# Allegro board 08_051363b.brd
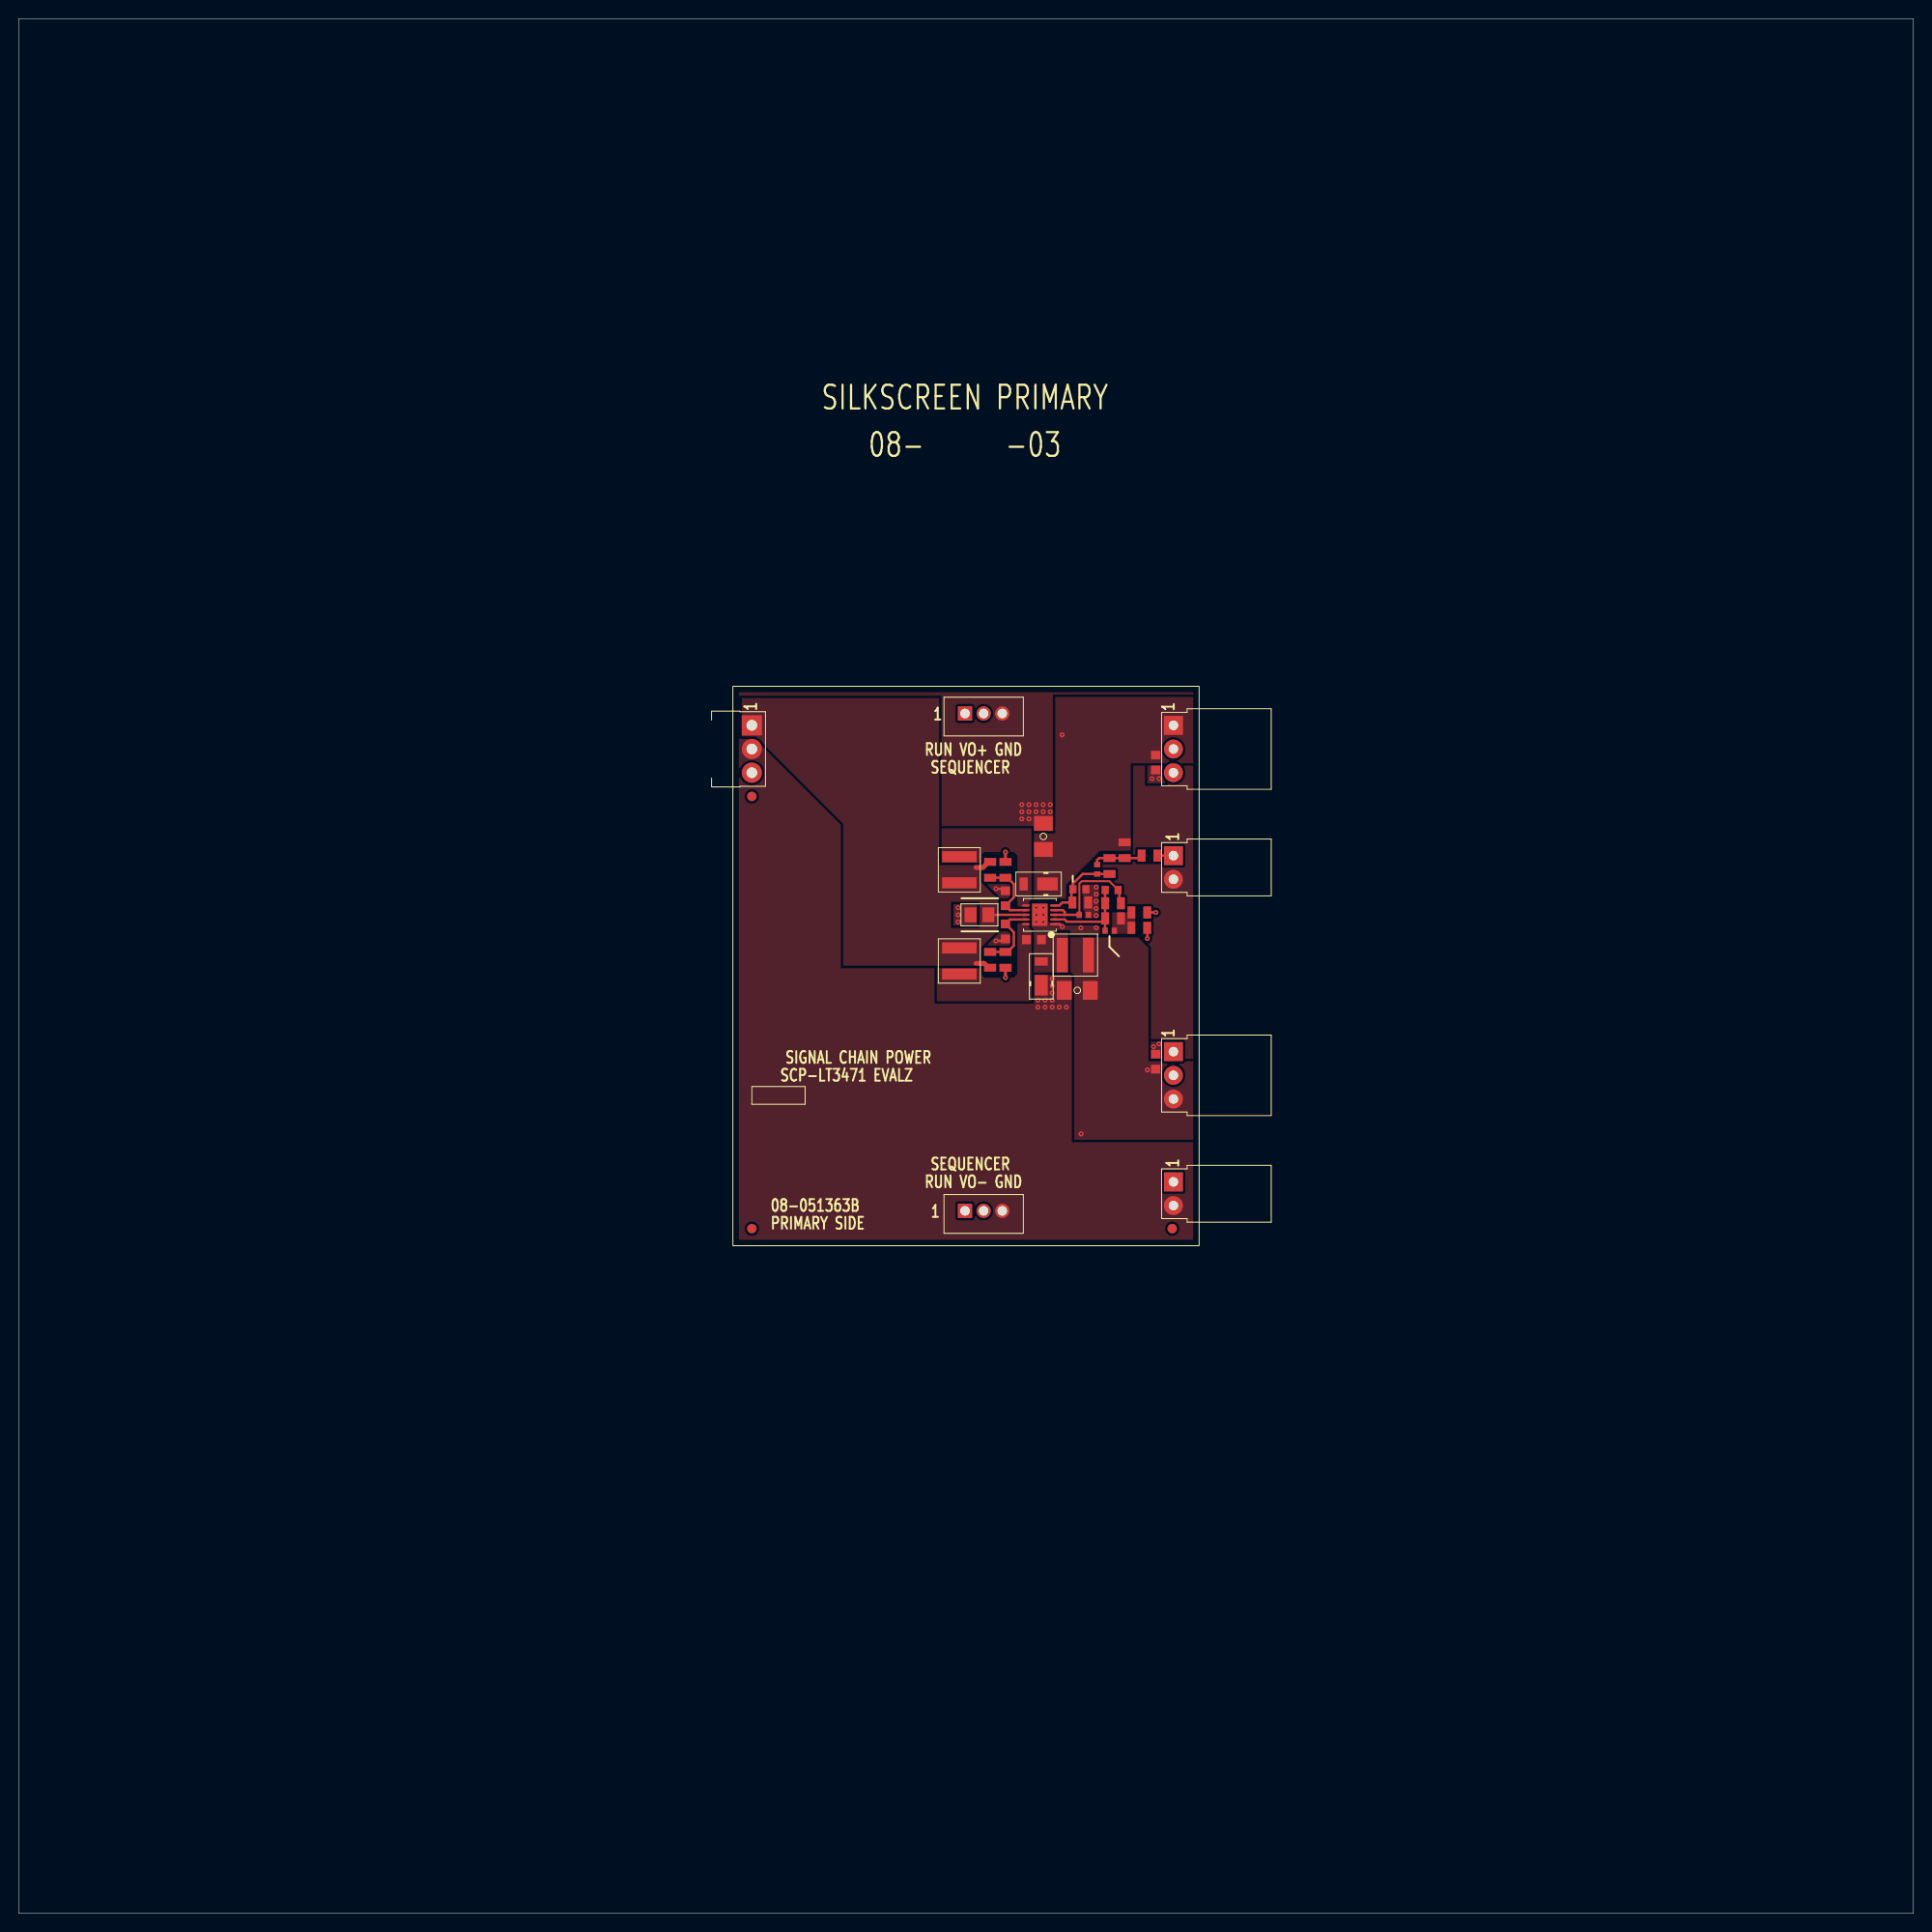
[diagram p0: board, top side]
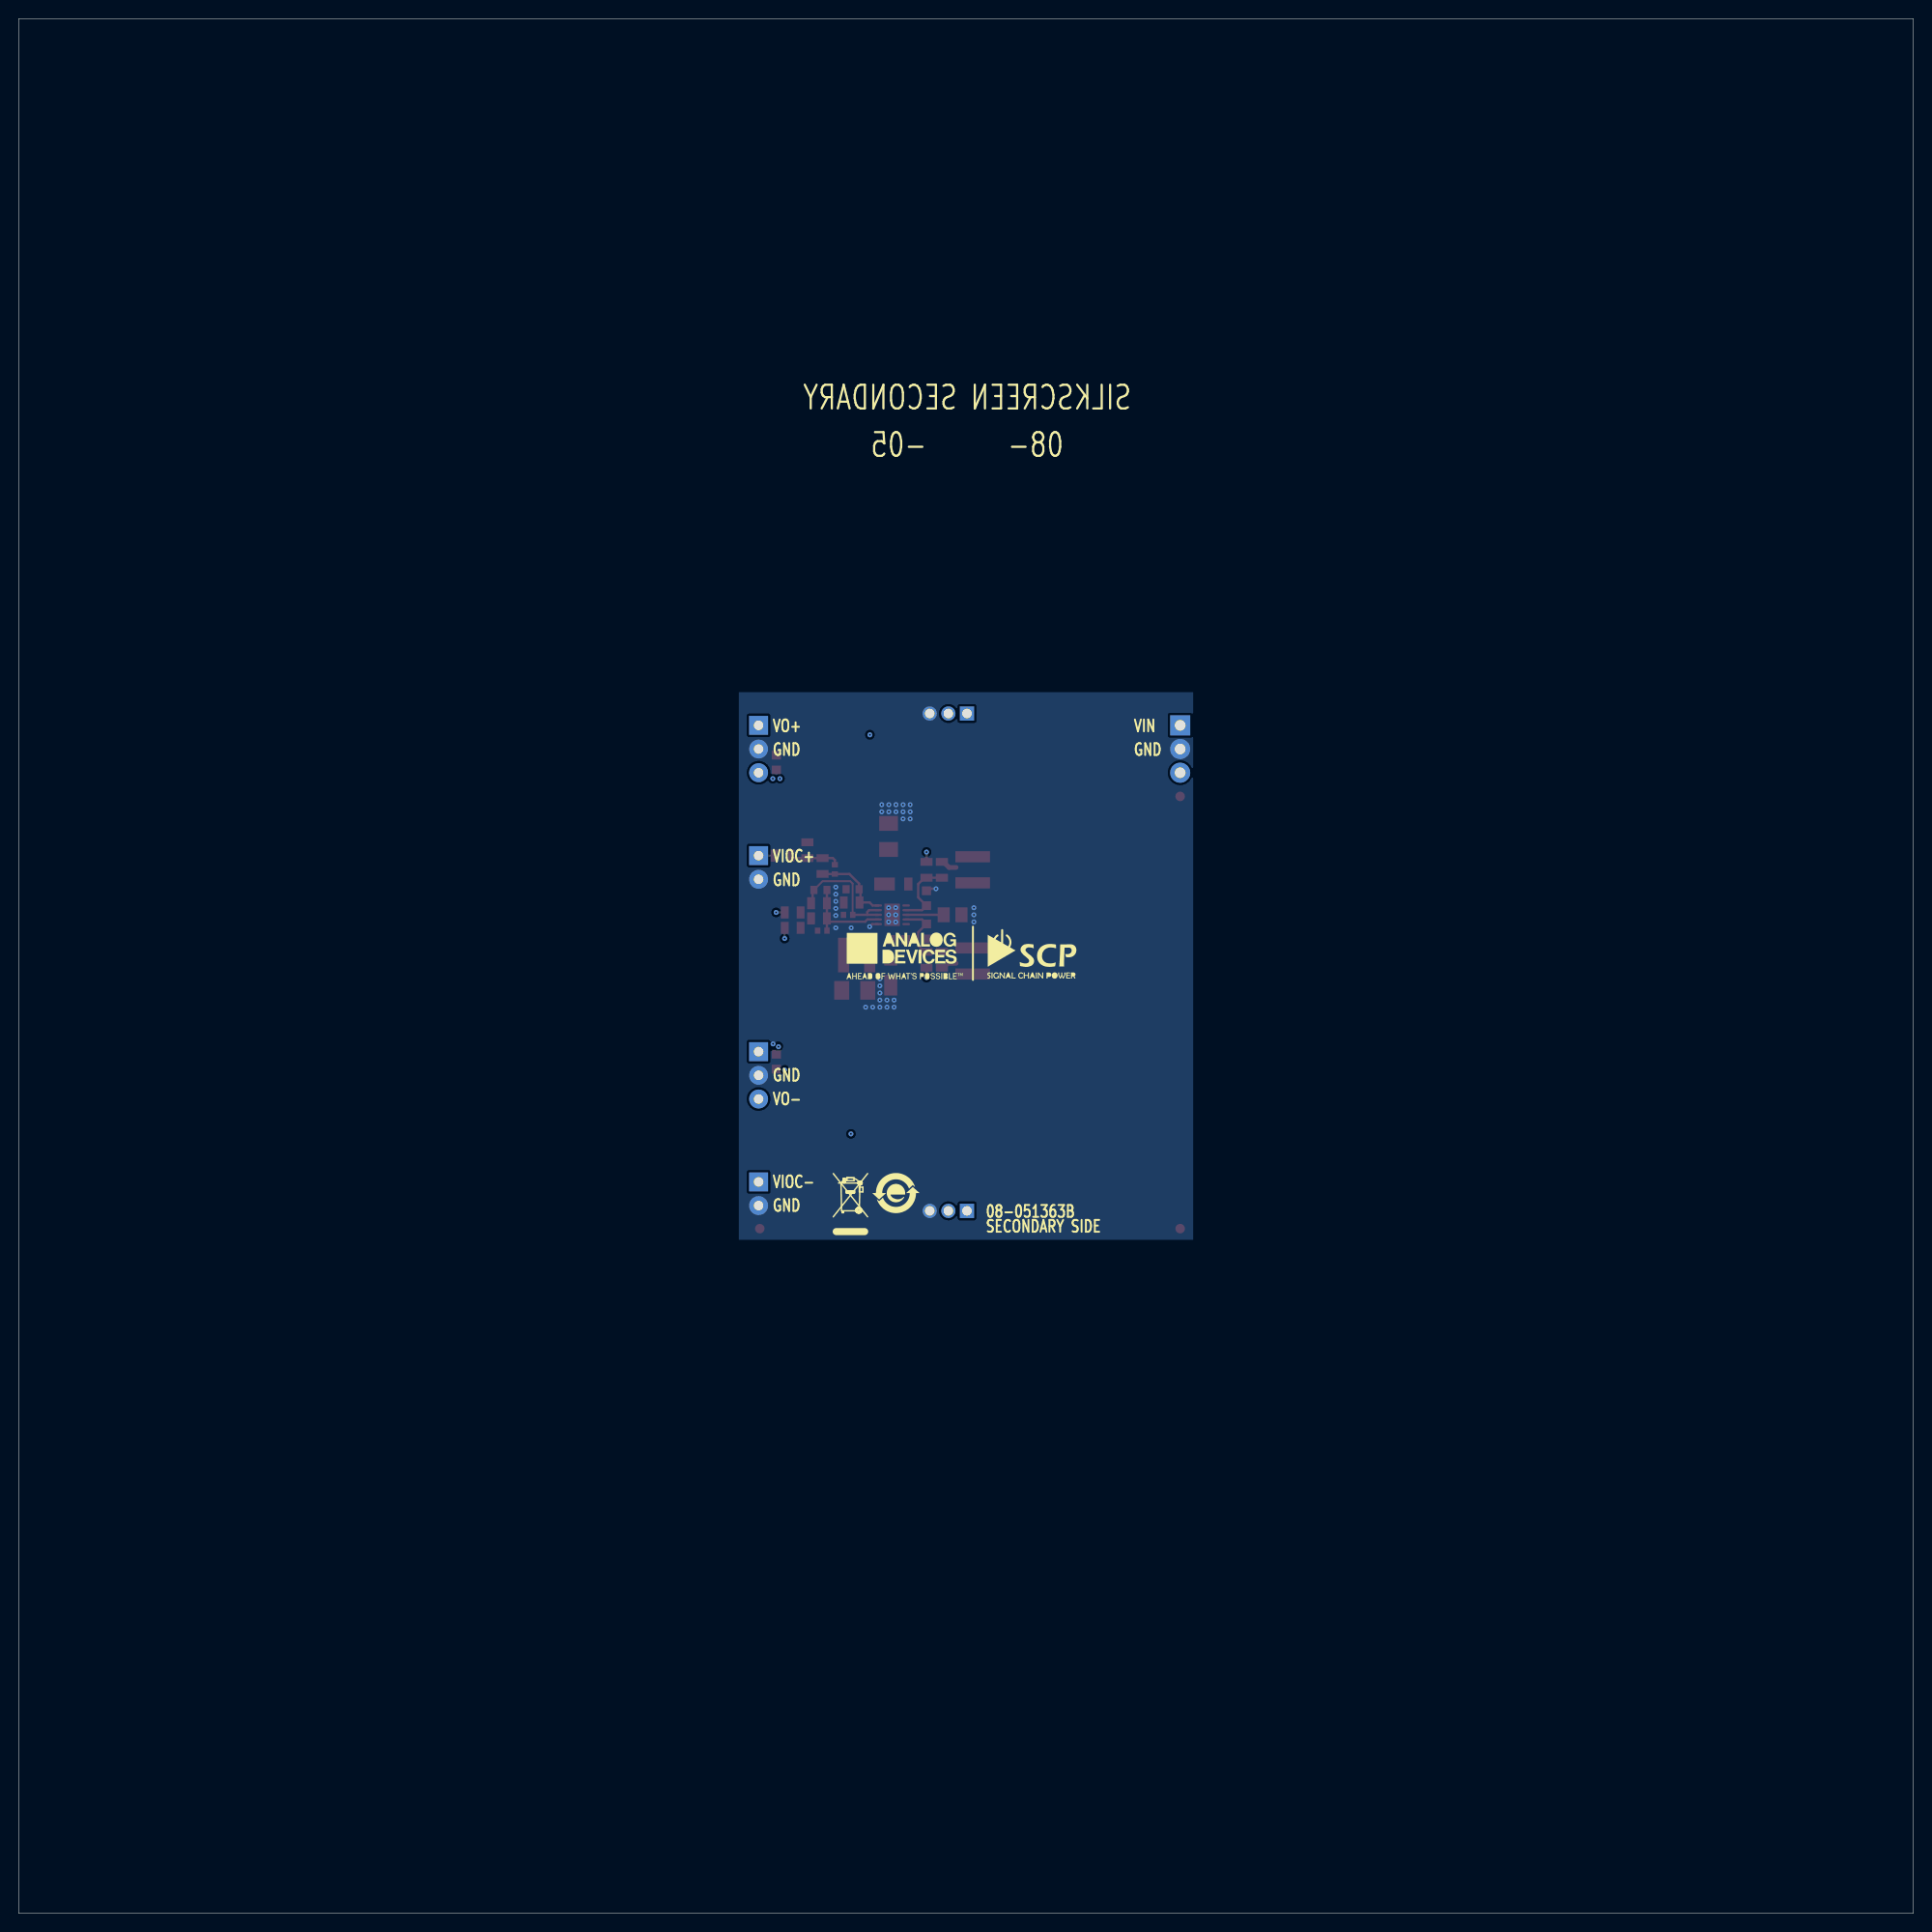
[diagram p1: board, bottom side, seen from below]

Outline 203.2 x 203.2 mm; copper layers: TOP, L2, L3, BOTTOM. Coordinates in mm from the lower left corner of the outline.
Outline path: 0,203.2 203.2,203.2 203.2,0 0,0 0,203.2

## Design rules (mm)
constraint set DEFAULT: min track width 0.203

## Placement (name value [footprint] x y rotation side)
C1  4.7UF  [C0805H53]  103.04 107.09 180 top
C2  0.1uF  [C0402]  114.24 107.09 0 top
C3  10UF  [C1206H71]  109.9 115.5 90 top
C4  10UF  [C1206H71]  113.53 98.99 180 top
C5  TBD0603  [C0603#2]  113.76 109.83 180 top
C6  1UF  [C0603]  121.94 123.42 270 top
C7  100PF  [C0402]  115.67 111.97 90 top
C9  1UF  [C0603]  121.94 91.34 90 top
C10  1UF  [C0603]  108.88 104.42 0 top
C11  100PF  [C0402]  117.01 105.39 0 top
C12  TBD0603  [C0603#2]  117.21 109.76 0 top
CSS1  0.33UF  [C0603]  105.84 105.31 270 top
CSS2  0.33UF  [C0603]  105.84 108.87 90 top
D1  DFLS120L-7  [POWERDI123]  109.39 110.39 180 top
D2  DFLS120L-7  [POWERDI123]  109.67 100.48 90 top
INPUT  PBC03SBAN  [CNTHMHDRRA1X3L300W100H145]  78.63 127.41 270 top
L1  10UH  [LSMSQ157H71-2]  100.88 111.91 270 top
L2  15UH  [LSMSQ157H47_PS]  100.88 102.14 90 top
L3  15UH  [LSMSQ157H47_PS]  113.33 102.77 0 top
NOREF  -  []  78.63 127.41 0 top
NOREF#2  -  []  76.6 131.6 270 top
NOREF#3  -  []  101.47 156.34 0 top
NOREF#4  -  [unnamed#2]  78.63 119.79 0 top
NOREF#5  -  [unnamed#2]  123.72 73.43 0 top
NOREF#6  -  []  76.6 71.6 0 top
NOREF#7  -  []  78.63 127.41 0 top
NOREF#8  -  []  161.82 133.76 0 top
NOREF#9  -  []  76.6 131.6 0 top
NOREF#10  -  []  126.6 71.6 90 top
NOREF#11  -  []  158.64 239.17 0 top
NOREF#12  -  []  214.14 74.07 0 top
NOREF#13  -  []  76.6 131.6 0 top
NOREF#14  -  []  -273.05 -196.85 0 top
NOREF#15  -  []  126.6 71.6 90 top
NOREF#16  -  []  -273.05 -196.85 0 top
NOREF#17  -  []  126.6 131.6 180 top
NOREF#18  -  []  53.87 15.01 0 top
NOREF#19  -  [unnamed#2]  78.63 73.43 0 top
NOREF#20  -  []  41.8 -101.19 0 top
NOREF#21  -  []  76.6 131.6 0 top
NOREF#22  -  []  114.19 72.8 180 bottom
NOREF#23  -  []  94.51 102.9 180 bottom
NOREF#24  -  []  109.11 77.24 180 bottom
NOREF#25  -  []  108.48 102.64 180 bottom
OUTPUT1  PPPC031LGBN-RC  [CNHDRRA1X3H108]  123.84 92.42 270 top
OUTPUT2  PPPC031LGBN-RC  [CNHDRRA1X3H108]  123.84 127.41 270 top
P1  53253-0370  [CNTHMHDR1X3L315W144H224]  101.49 75.34 0 top
P2  53253-0370  [CNTHMHDR1X3L315W144H224]  101.49 128.68 0 top
R1  54.9K  [R0805]  116.99 112.32 270 top
R2  4.99K  [R0805]  113.86 108.41 180 top
R5  182K  [R0805]  117.37 106.71 0 top
R6  15K  [R0805]  117.37 108.33 0 top
R7  TBD0805  [R0805]  121.28 113.44 180 top
R8  TBD0805  [R0805]  120.19 107.34 0 top
R9  0  [R0805]  118.61 114.02 90 top
R10  0  [R0805]  120.19 105.69 0 top
R11  TBD0805  [R0805]  105.84 111.91 270 top
R12  TBD0805  [R0805]  105.84 102.26 90 top
RSS1  4.7K  [R0805]  104.18 102.26 90 top
RSS2  4.7K  [R0805]  104.18 111.91 270 top
U1  LT3471EDD#PBF  [QFN10_3X3_PAD2_38X1_64]  109.52 107.09 90 top
VIOC+  PPPC021LGBN-RC  [CNTHFHDRRA1X2L220W335H108]  123.84 113.44 270 top
VIOC-  PPPC021LGBN-RC  [CNTHFHDRRA1X2L220W335H108]  123.84 78.45 270 top

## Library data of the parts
C1 = CAP: Tolerance: 10; User Part Number: UPN; alternate symbols: (); part number: CAP_SM-4.7UF,25V,10,E034916,C0805H53; tolerance: 10
C2 = CAP: User Part Number: UPN; Tolerance: 10; alternate symbols: (); part number: CAP_SM-0.1UF,16V,10,E018707,C0402; tolerance: 10
C3 C4 = CAP: Tolerance: 20; User Part Number: UPN; alternate symbols: (); part number: CAP_SM-10UF,50V,20,E035601,C1206H71; tolerance: 20
C5 C12 = CAP: User Part Number: UPN; alternate symbols: (C0603L, C0603L_ALT); part number: CAP_SM-TBD0603,TBD0603,TBD0603,E000382,C0603
C6 C9 C10 = CAP: User Part Number: UPN; Tolerance: 10; alternate symbols: (); part number: CAP_SM-1UF,50V,10,E034224,C0603; tolerance: 10
C7 C11 = CAP: User Part Number: UPN; Tolerance: 1; alternate symbols: (); part number: CAP_SM-100PF,50V,1,E033808,C0402; tolerance: 1
CSS1 CSS2 = CAP: User Part Number: UPN; Tolerance: 20; alternate symbols: (); part number: CAP_SM-0.33UF,16V,10,E033782,C0603; tolerance: 20
D1 D2 = DIOSCHOTTKY: User Part Number: UPN; Tolerance: N/A; alternate symbols: (); part number: DIOSCHOTTKY_SM-DFLS120L-7,20V,N/A,E033687,POWERDI123; tolerance: N/A
INPUT = CN3P: Tolerance: N/A; User Part Number: UPN; alternate symbols: (CNTHMHDRRA1X3L300W100H145_SCP); part number: CN3P_TH-PBC03SBAN,E034137,CNTHMHDRRA1X3L300W100H145; tolerance: N/A
L1 = IND: User Part Number: UPN; Tolerance: 20; alternate symbols: (); part number: IND_SM-10UH,20,E032200,LSMSQ157H71-2; tolerance: 20
L2 L3 = IND: User Part Number: UPN; Tolerance: 20; alternate symbols: (); part number: IND_SM-15UH,20,E032207,LSMSQ157H47_PS; tolerance: 20
OUTPUT1 OUTPUT2 = CN3P: User Part Number: UPN; Tolerance: N/A; alternate symbols: (CNHDRRA1X3H108_SCP); part number: CN3P_TH-PPPC031LGBN-RC,E034111,CNHDRRA1X3H108; tolerance: N/A
P1 P2 = CN3P: Tolerance: N/A; User Part Number: UPN; alternate symbols: (); part number: CN3P_TH-53253-0370,E033940,CNTHMHDR1X3L315W144H224; tolerance: N/A
R1 = RES: User Part Number: UPN; Tolerance: 1; alternate symbols: (R0805L); part number: RES_SM-54.9K,E033779,1/8W,1,R0805; tolerance: 1
R2 = RES: User Part Number: UPN; Tolerance: 1; alternate symbols: (R0805L); part number: RES_SM-4.99K,E003493,1/8W,1,R0805; tolerance: 1
R5 = RES: User Part Number: UPN; Tolerance: 1; alternate symbols: (R0805L); part number: RES_SM-182K,E014265,1/8W,1,R0805; tolerance: 1
R6 = RES: User Part Number: UPN; Tolerance: 0.1; alternate symbols: (R0805L); part number: RES_SM-15K,E003804,1/8W,0.1,R0805; tolerance: 0.1
R7 R8 R11 R12 = RES: User Part Number: UPN; alternate symbols: (R0805L); part number: RES_SM-TBD0805,E004051,TBD0805,TBD0805,R0805
R9 R10 = RES: User Part Number: UPN; Tolerance: N/A; alternate symbols: (R0805L); part number: RES_SM-0,E030875,1/8W,N/A,R0805; tolerance: N/A
RSS1 RSS2 = RES: User Part Number: UPN; Tolerance: 5; alternate symbols: (R0805L); part number: RES_SM-4.7K,E010737,1/8W,5,R0805; tolerance: 5
U1 = LINLT3471: User Part Number: UPN; Tolerance: N/A; alternate symbols: (); part number: LINLT3471_SM-LT3471EDD#PBF,E030330,QFN10_3X3_PAD2_38X1_64; tolerance: N/A
VIOC+ VIOC- = CN2P: Tolerance: N/A; User Part Number: UPN; alternate symbols: (CNTHFHDRRA1X2L220W335H108_SCP); part number: CN2P_TH-PPPC021LGBN-RC,E034113,CNTHFHDRRA1X2L220W335H108; tolerance: N/A

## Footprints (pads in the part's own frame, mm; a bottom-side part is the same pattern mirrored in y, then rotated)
C0402
  rect 0.584x0.66 smd: 1(-0.5,0) 2(0.5,0)
C0603
  rect 0.94x0.991 smd: 1(-0.8,0) 2(0.8,0)
C0603#2
  rect 0.762x0.889 smd: 1(-0.7,0) 2(0.7,0)
C0805H53
  rect 1.295x1.6 smd: 1(-0.953,0) 2(0.953,0)
C1206H71
  rect 1.6x2.007 smd: 1(-1.397,0) 2(1.397,0)
CNHDRRA1X3H108
  rect 2.032x2.032 hole 1.016: 1(0,0)
  round 2.032 hole 1.016: 2(2.54,0) 3(5.08,0)
CNTHFHDRRA1X2L220W335H108
  rect 2.032x2.032 hole 1.016: 1(0,0)
  round 2.032 hole 1.016: 2(2.54,0)
CNTHMHDR1X3L315W144H224
  rect 1.524x1.524 hole 1.016: 1(0,0)
  round 1.524 hole 1.016: 2(2,0) 3(4,0)
CNTHMHDRRA1X3L300W100H145
  rect 2.159x2.159 hole 1.143: 1(0,0)
  round 2.159 hole 1.143: 2(2.54,0) 3(5.08,0)
LSMSQ157H47_PS
  rect 1.194x3.708 smd: 1(-1.4,0) 2(1.4,0)
LSMSQ157H71-2
  rect 1.194x3.708 smd: 1(-1.4,0) 2(1.4,0)
POWERDI123
  rect 0.889x1.397 smd: A(1.606,0)
  rect 2.21x1.397 smd: C(-0.945,0)
QFN10_3X3_PAD2_38X1_64
  oval 0.254x0.813 smd: 1(-1,-1.5) 2(-0.5,-1.5) 3(0,-1.5) 4(0.5,-1.5) 5(1,-1.5) 6(1,1.5) 7(0.5,1.5) 8(0,1.5) 9(-0.5,1.5) 10(-1,1.5)
  rect 2.388x1.651 smd: PAD(0,0)
R0805
  rect 0.838x1.295 smd: 1(-0.85,0) 2(0.85,0)
unnamed#2
  round 1.016 smd: (0,0)

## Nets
GND: C1.2(N2) C2.2(N2) C3.2(N2) C4.2(N2) C5.1 C6.2(N2) C9.2(N2) CSS1.2(N2) CSS2.2(N2) D2.C INPUT.2 OUTPUT1.2 OUTPUT2.2 P1.3(N3) P2.3(N3) R2.1 U1.1 U1.PAD VIOC+.2(N2) VIOC-.2(N2)
VIN: C1.1 INPUT.1 L1.2(N2) L2.2(N2) RSS1.1 RSS2.1 U1.8
UNNAMED_2_CAP_I17_N2: C5.2(N2) C7.1 R1.2(N2) R2.2(N2) U1.5
UNNAMED_2_CAP_I19_N1: CSS2.1 R11.2(N2) RSS2.2(N2) U1.7
UNNAMED_2_CAP_I26_N1: CSS1.1 R12.2(N2) RSS1.2(N2) U1.9
UNNAMED_2_CAP_I28_N1: C2.1 C12.2(N2) R6.2(N2) U1.3(VREF) U1.4
UNNAMED_2_CAP_I31_N2: C7.2(N2) R1.1 R7.2(N2) R9.1
UNNAMED_2_CAP_I35_N1: C11.1 C12.1 R5.1 R6.1 U1.2
UNNAMED_2_CAP_I36_N1: C10.1 L2.1 U1.10
UNNAMED_2_CAP_I36_N2: C10.2(N2) D2.A(P) L3.1
UNNAMED_2_CAP_I40_N2: C11.2(N2) R5.2(N2) R8.1 R10.1
UNNAMED_2_CN3P_I1_N1: P1.1 R12.1
UNNAMED_2_CN3P_I6_N1: P2.1 R11.1
UNNAMED_2_DIOSCHOTTKY_I34_P: D1.A(P) L1.1 U1.6
VIOC+: R7.1 VIOC+.1
VIOC-: R8.2(N2) VIOC-.1
VO+: C3.1 C6.1 D1.C OUTPUT2.1 P2.2 R9.2(N2)
VO-: C4.1 C9.1 L3.2(N2) OUTPUT1.3(N3) P1.2 R10.2(N2)

Pads without a net: INPUT 3; OUTPUT1 1; OUTPUT2 3

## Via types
v1: diameter 0.533, hole 0.203, TOP to BOTTOM, 53 vias

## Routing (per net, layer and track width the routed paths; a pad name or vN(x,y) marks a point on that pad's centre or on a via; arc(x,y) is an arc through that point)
GND: length 3.2
  TOP w0.254: v1(104.82,109.88) 105.62,109.88 CSS2.2 ; U1.1 111.66,106.09 v1(111.93,105.82) ; CSS1.2 105.62,104.29 v1(104.82,104.29)
  vias: v1(100.76,107.85) v1(100.76,107.09) v1(100.76,106.33) v1(107.59,118.9) v1(107.59,118.14) v1(107.59,117.38) v1(108.35,118.9) v1(108.35,118.14) v1(108.35,117.38) v1(109.11,118.9) v1(109.11,118.14) v1(109.14,107.85) v1(109.14,107.09) v1(109.14,106.33) v1(109.32,97.94) v1(109.32,97.18) v1(109.87,118.9) v1(109.87,118.14) v1(109.9,107.85) v1(109.9,107.09) v1(109.9,106.33) v1(110.08,97.94) v1(110.08,97.18) v1(110.64,118.9) v1(110.64,118.14) v1(110.84,100.23) v1(110.84,99.47) v1(110.84,98.71) v1(110.84,97.94) v1(110.84,97.18) v1(111.6,97.18) v1(112.36,97.18) v1(113.91,105.69) v1(115.56,110.06) v1(115.56,109.3) v1(115.56,108.54) v1(115.56,107.77) v1(115.56,107.01) v1(115.56,105.69) v1(121.56,121.69) v1(121.71,92.94) v1(122.32,121.69) v1(122.29,93.25)
VIN: length 7.5
  TOP w0.254: U1.8 C1.1
  TOP w0.508: RSS1.1 104.02,101.41 103.55,101.88 102.66,101.88 ; RSS2.1 104.02,112.76 103.42,112.17 102.66,112.17
UNNAMED_2_CAP_I17_N2: length 8.6
  TOP w0.254: U1.5 111.61,108.09 111.93,108.41 R2.2 112.91,108.51 112.91,109.68 C5.2 113.06,110.43 114.1,111.47 C7.1 116.98,111.47 R1.2
UNNAMED_2_CAP_I19_N1: length 7.9
  TOP w0.254: RSS2.2 R11.2 106.05,111.07 106.72,110.39 106.72,108.96 CSS2.1 106.31,107.59 U1.7
UNNAMED_2_CAP_I26_N1: length 7.9
  TOP w0.254: RSS1.2 R12.2 106.05,103.11 106.72,103.79 106.72,105.22 CSS1.1 106.31,106.59 U1.9
UNNAMED_2_CAP_I28_N1: length 13.8
  TOP w0.203: C12.2 116.97,110.7 114.01,110.7 113.76,110.44 113.76,107.11 C2.1
  TOP w0.254: 112.19,107.09 U1.3 ; 112.19,107.09 112.19,107.39 111.99,107.59 U1.4 ; 112.19,107.09 C2.1 ; C12.2 118.05,109.62 118.05,108.5 R6.2
UNNAMED_2_CAP_I31_N2: length 5.5
  TOP w0.254: R7.2 120.16,113.17 R9.1 118.61,113.17 R1.1 115.88,113.17 115.67,112.96 C7.2
UNNAMED_2_CAP_I35_N1: length 10.1
  TOP w0.254: R5.1 116.52,105.39 C11.1 ; R5.1 116.16,106.35 112.41,106.35 112.18,106.59 U1.2 ; R5.1 R6.1 116.52,109.75 C12.1
UNNAMED_2_CN3P_I1_N1: length 27.9
  TOP w0.305: R12.1 v1(105.84,100.36)
  L3 w0.254: v1(105.84,100.36) 101.49,96.01 P1.1
UNNAMED_2_CN3P_I6_N1: length 17.7
  TOP w0.305: R11.1 v1(105.84,113.82)
  L3 w0.254: P2.1 101.49,118.16 v1(105.84,113.82)
VIOC+: length 1.7
  TOP w0.254: R7.1 VIOC+.1
VIOC-: length 31.9
  TOP w0.254: R8.2 v1(121.96,107.34)
  L3 w0.254: v1(121.96,107.34) 125.37,103.94 125.37,79.97 VIOC-.1
VO+: length 9.4
  L3 w0.305: P2.2 105.78,126.39 v1(111.91,126.39)
VO-: length 29.1
  TOP w0.254: v1(121.05,104.55) 121.05,105.68 R10.2
  L3 w0.254: v1(121.05,104.55) v1(121.05,90.45)
  L3 w0.305: P1.2 111.75,83.59 v1(113.94,83.59)

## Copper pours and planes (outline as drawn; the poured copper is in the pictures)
GND on TOP: 121.05,123.09 121.05,121.19 122.96,121.19 122.96,123.09
GND on TOP: 102.79,108.23 102.79,105.95 100.25,105.95 100.25,108.23
GND on TOP: 121.43,91.67 121.43,93.5 122.83,93.5 122.83,91.67
GND on TOP: 77.24,130.96 125.96,130.96 125.96,72.24 77.24,72.24 ; 10 cut-outs
GND on BOTTOM, L3: 77.24,130.96 125.96,130.96 125.96,72.24 77.24,72.24 ; 4 cut-outs
GND on L2: 77.24,130.96 125.96,130.96 125.96,130.71 110.92,130.71 110.92,117.86 111.17,117.86 111.17,130.46 125.96,130.46 125.96,123.34 122.96,123.34 122.96,121.19 121.05,121.19 121.05,123.34 119.27,123.34 119.27,113.95 115.97,113.95 112.34,110.31 112.34,108.82 108.88,108.82 108.88,115.83 108.63,115.83 108.63,108.56 112.59,108.56 112.59,110.19 116.1,113.69 119.53,113.69 119.53,123.09 120.8,123.09 120.8,120.93 123.21,120.93 123.21,123.09 125.96,123.09 125.96,91.65 123.08,91.65 123.08,93.75 121.43,93.75 121.43,103.66 120.16,104.93 112.54,104.93 112.54,100.89 112.95,100.48 113.2,100.48 113.2,100.59 112.8,100.99 112.8,104.68 120.03,104.68 121.18,103.53 121.18,91.39 121.43,91.39 121.43,93.5 122.83,93.5 122.83,91.39 125.96,91.39 125.96,82.96 113.2,82.96 113.2,96.9 112.95,96.9 112.95,82.7 125.96,82.7 125.96,72.24 77.24,72.24
VIN on TOP: 98.72,112.42 103.17,112.42 103.17,110.64 105.07,108.74 105.07,105.44 103.17,103.53 103.17,101.63 88.44,101.63 88.44,116.84 79.06,126.22 77.57,126.22 77.57,130.33 98.72,130.33
UNNAMED_2_CAP_I36_N1 on TOP: 108.38,106.2 107.23,106.2 107.11,106.07 107.11,100.74 106.72,100.36 103.55,100.36 103.3,100.61 103.3,101.37 98.47,101.37 98.47,97.82 108.63,97.82 108.63,105.44 108.38,105.69
UNNAMED_2_CAP_I36_N2 on TOP: 108.88,105.18 108.88,100.92 112.52,100.92 112.52,105.18
UNNAMED_2_CAP_I40_N2 on TOP: 117.27,105.06 117.27,107.34 118.79,107.34 118.92,107.47 118.92,107.98 119.73,107.98 119.73,105.06
UNNAMED_2_DIOSCHOTTKY_I34_P on TOP: 108.38,107.95 107.26,107.95 107.11,108.1 107.11,113.44 106.72,113.82 103.55,113.82 103.3,113.57 103.3,112.68 98.98,112.68 98.98,116.36 108.63,116.36 108.63,108.74 108.38,108.49
VO+ on TOP: 119.27,123.34 119.27,113.95 115.97,113.95 112.34,110.31 112.34,108.82 108.88,108.82 108.88,115.83 111.17,115.83 111.17,130.46 125.96,130.46 125.96,123.34
VO- on TOP: 120.03,104.68 121.18,103.53 121.18,91.39 125.96,91.39 125.96,82.96 113.2,82.96 113.2,100.59 112.8,100.99 112.8,104.68

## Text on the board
Ref Des/Silkscreen Bottom: VIN | GND | 08-051363B | SECONDARY SIDE | VO+ | VIOC+ | VO- | VIOC-
User.Comments: WITH LEAD-FREE AND RoHS PCB ASSEMBLY STANDARDS (EU RoHS | DIRECTIVE 2002/95/EC). | 4.    RoHS COMPLIANCE: ASSEMBLY VENDOR SHOULD ASSURE COMPLIANCE
Ref Des/Silkscreen Top: 08-051363B | PRIMARY SIDE | RUN VO+ GND | RUN VO- GND | SEQUENCER | SCP-LT3471 EVALZ | SIGNAL CHAIN POWER
PAGE_OUTLINE: B | AS PER ECR-086561 | 07MAY19 | J. VIERNES
DIMENSION: REF
User.15: PER IPC-4552 LATEST REVISION | 15.    THRU VIAS TO BE FILLED WITH SOLDERMASK | SEE FAB NOTE 15 | DIA MAX
User.17: 08-      -07 | L2
User.18: L3 | 08-      -08
User.45: FIGURE | SIZE | 8.0 | 40.0 | 45.0 | PLATED | FINISHED HOLES IN MILS | ALL UNITS ARE IN MILS | QTY | 53 | 16 | 3 | TOLERANCE/NOTES
